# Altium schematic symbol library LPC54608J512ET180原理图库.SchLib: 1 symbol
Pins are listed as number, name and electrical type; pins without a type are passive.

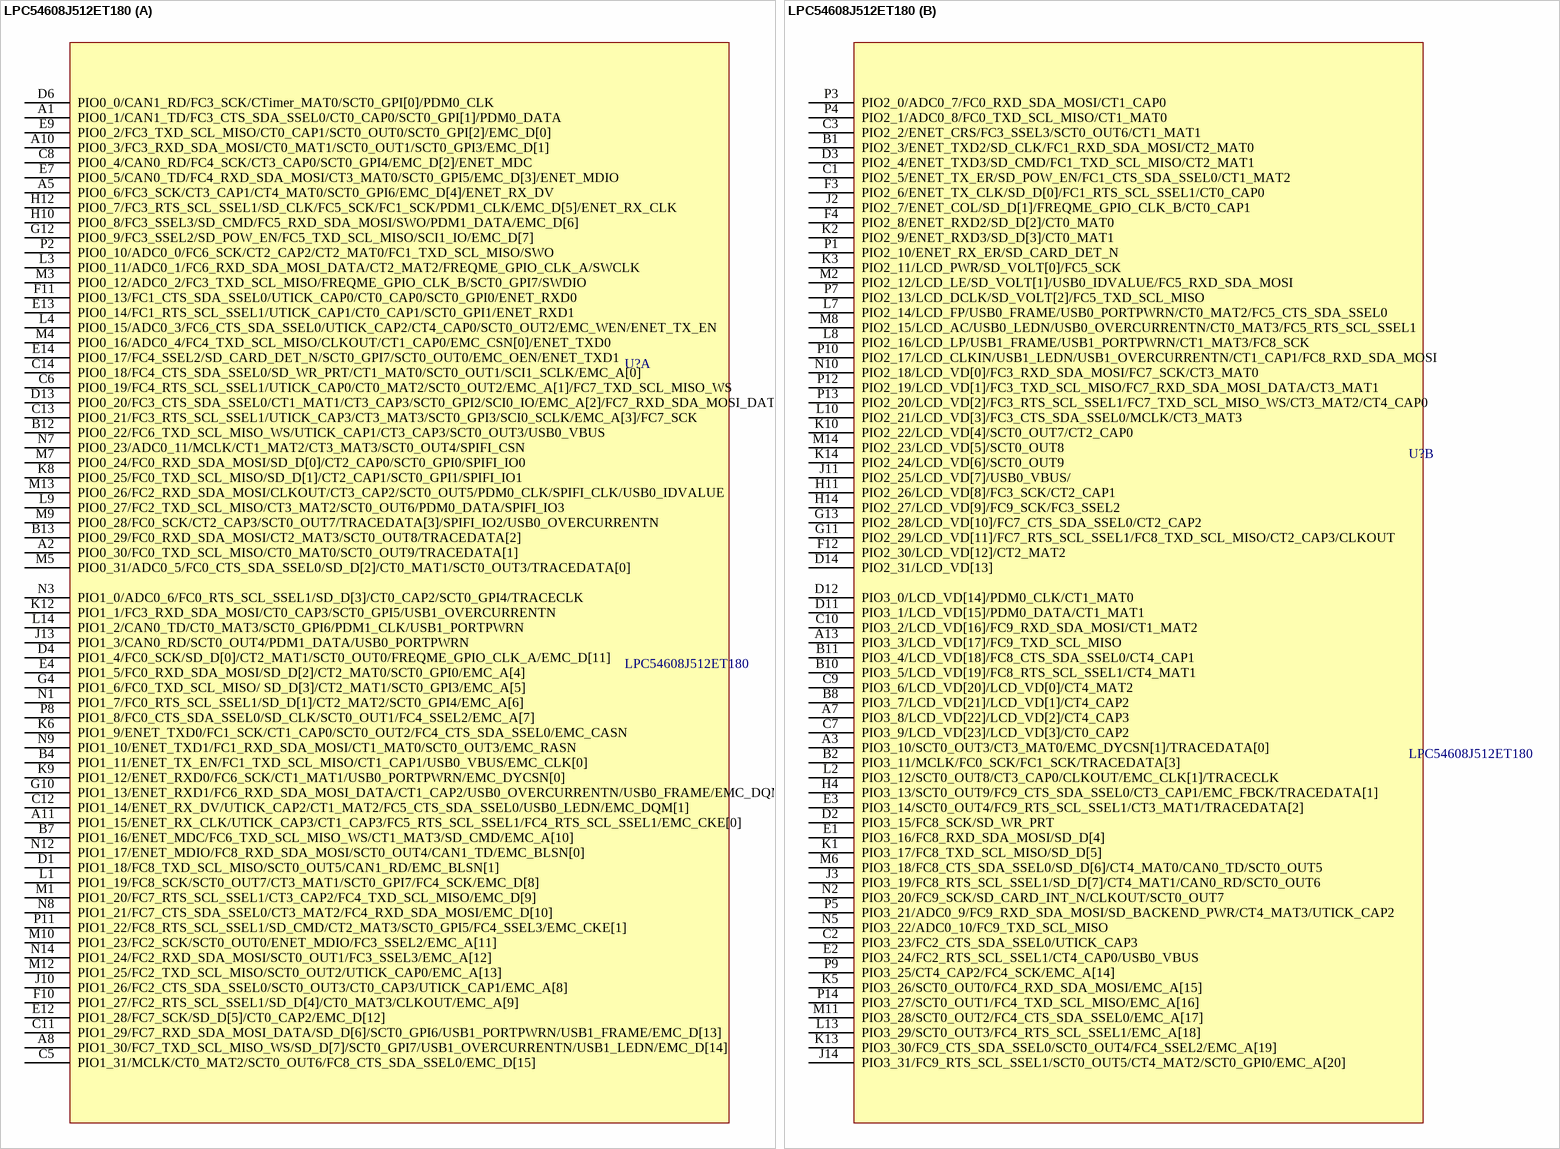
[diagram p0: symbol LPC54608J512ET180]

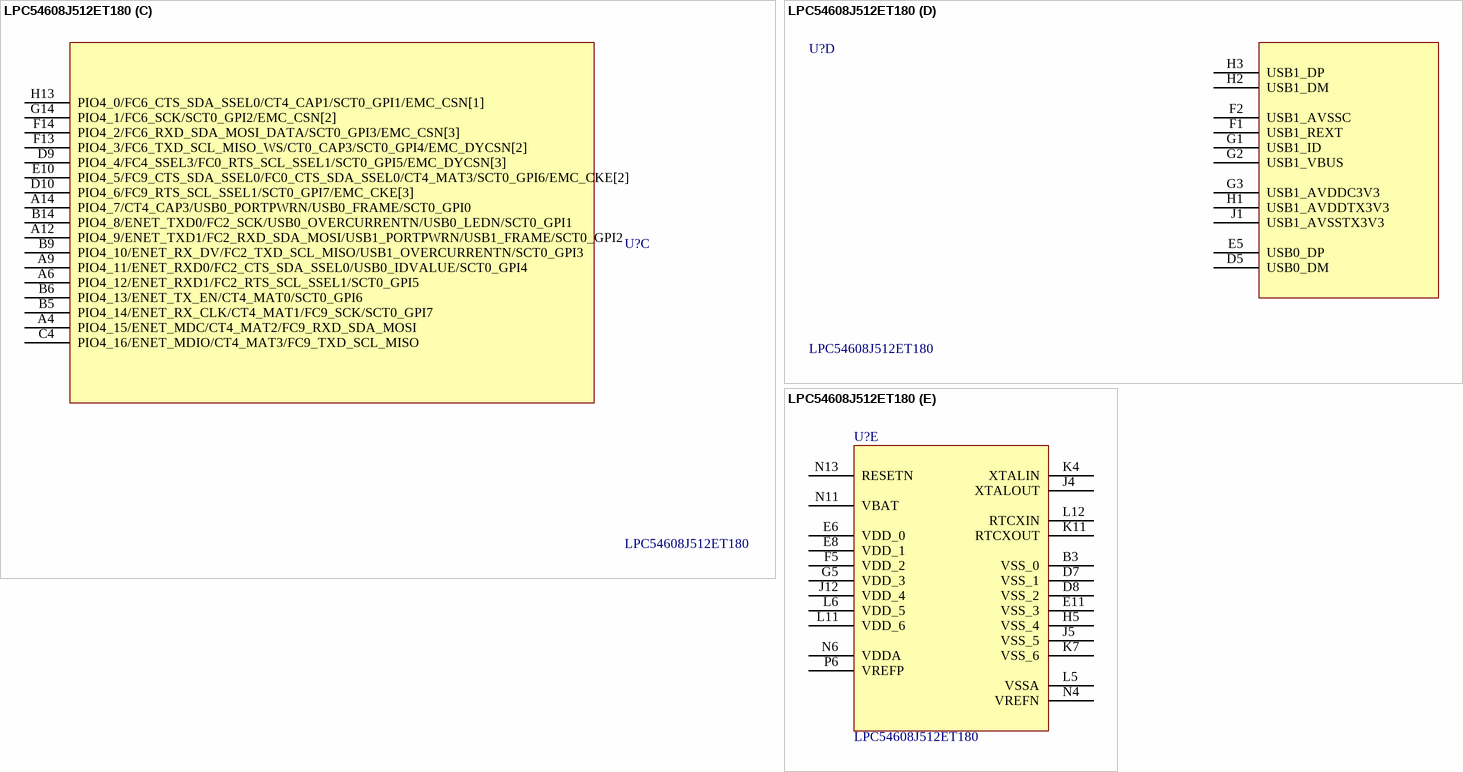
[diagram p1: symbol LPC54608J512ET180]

## LPC54608J512ET180
designator U?
LPC54608J512ET180,TFBGA180,NXP,RoHS; 物料代码: 1.05.02.0192; 名称: 集成电路(临时); 贴片和直插: SMT; PCB备注: 170314lmd; 器件优选方案: 临时/偏门物料/不主推物料，谨慎选用
footprint BGA180C80P14x14
part A pins: A1 PIO0_1/CAN1_TD/FC3_CTS_SDA_SSEL0/CT0_CAP0/SCT0_GPI[1]/PDM0_DATA, A2 PIO0_30/FC0_TXD_SCL_MISO/CT0_MAT0/SCT0_OUT9/TRACEDATA[1], A5 PIO0_6/FC3_SCK/CT3_CAP1/CT4_MAT0/SCT0_GPI6/EMC_D[4]/ENET_RX_DV, A8 PIO1_30/FC7_TXD_SCL_MISO_WS/SD_D[7]/SCT0_GPI7/USB1_OVERCURRENTN/USB1_LEDN/EMC_D[14], A10 PIO0_3/FC3_RXD_SDA_MOSI/CT0_MAT1/SCT0_OUT1/SCT0_GPI3/EMC_D[1], A11 PIO1_15/ENET_RX_CLK/UTICK_CAP3/CT1_CAP3/FC5_RTS_SCL_SSEL1/FC4_RTS_SCL_SSEL1/EMC_CKE[0], B4 PIO1_11/ENET_TX_EN/FC1_TXD_SCL_MISO/CT1_CAP1/USB0_VBUS/EMC_CLK[0], B7 PIO1_16/ENET_MDC/FC6_TXD_SCL_MISO_WS/CT1_MAT3/SD_CMD/EMC_A[10], B12 PIO0_22/FC6_TXD_SCL_MISO_WS/UTICK_CAP1/CT3_CAP3/SCT0_OUT3/USB0_VBUS, B13 PIO0_29/FC0_RXD_SDA_MOSI/CT2_MAT3/SCT0_OUT8/TRACEDATA[2], C5 PIO1_31/MCLK/CT0_MAT2/SCT0_OUT6/FC8_CTS_SDA_SSEL0/EMC_D[15], C6 PIO0_19/FC4_RTS_SCL_SSEL1/UTICK_CAP0/CT0_MAT2/SCT0_OUT2/EMC_A[1]/FC7_TXD_SCL_MISO_WS, C8 PIO0_4/CAN0_RD/FC4_SCK/CT3_CAP0/SCT0_GPI4/EMC_D[2]/ENET_MDC, C11 PIO1_29/FC7_RXD_SDA_MOSI_DATA/SD_D[6]/SCT0_GPI6/USB1_PORTPWRN/USB1_FRAME/EMC_D[13], C12 PIO1_14/ENET_RX_DV/UTICK_CAP2/CT1_MAT2/FC5_CTS_SDA_SSEL0/USB0_LEDN/EMC_DQM[1], C13 PIO0_21/FC3_RTS_SCL_SSEL1/UTICK_CAP3/CT3_MAT3/SCT0_GPI3/SCI0_SCLK/EMC_A[3]/FC7_SCK, C14 PIO0_18/FC4_CTS_SDA_SSEL0/SD_WR_PRT/CT1_MAT0/SCT0_OUT1/SCI1_SCLK/EMC_A[0], D1 PIO1_18/FC8_TXD_SCL_MISO/SCT0_OUT5/CAN1_RD/EMC_BLSN[1], D4 PIO1_4/FC0_SCK/SD_D[0]/CT2_MAT1/SCT0_OUT0/FREQME_GPIO_CLK_A/EMC_D[11], D6 PIO0_0/CAN1_RD/FC3_SCK/CTimer_MAT0/SCT0_GPI[0]/PDM0_CLK, D13 PIO0_20/FC3_CTS_SDA_SSEL0/CT1_MAT1/CT3_CAP3/SCT0_GPI2/SCI0_IO/EMC_A[2]/FC7_RXD_SDA_MOSI_DATA, E4 PIO1_5/FC0_RXD_SDA_MOSI/SD_D[2]/CT2_MAT0/SCT0_GPI0/EMC_A[4], E7 PIO0_5/CAN0_TD/FC4_RXD_SDA_MOSI/CT3_MAT0/SCT0_GPI5/EMC_D[3]/ENET_MDIO, E9 PIO0_2/FC3_TXD_SCL_MISO/CT0_CAP1/SCT0_OUT0/SCT0_GPI[2]/EMC_D[0], E12 PIO1_28/FC7_SCK/SD_D[5]/CT0_CAP2/EMC_D[12], E13 PIO0_14/FC1_RTS_SCL_SSEL1/UTICK_CAP1/CT0_CAP1/SCT0_GPI1/ENET_RXD1, E14 PIO0_17/FC4_SSEL2/SD_CARD_DET_N/SCT0_GPI7/SCT0_OUT0/EMC_OEN/ENET_TXD1, F10 PIO1_27/FC2_RTS_SCL_SSEL1/SD_D[4]/CT0_MAT3/CLKOUT/EMC_A[9], F11 PIO0_13/FC1_CTS_SDA_SSEL0/UTICK_CAP0/CT0_CAP0/SCT0_GPI0/ENET_RXD0, G4 PIO1_6/FC0_TXD_SCL_MISO/ SD_D[3]/CT2_MAT1/SCT0_GPI3/EMC_A[5], G10 PIO1_13/ENET_RXD1/FC6_RXD_SDA_MOSI_DATA/CT1_CAP2/USB0_OVERCURRENTN/USB0_FRAME/EMC_DQM[0], G12 PIO0_9/FC3_SSEL2/SD_POW_EN/FC5_TXD_SCL_MISO/SCI1_IO/EMC_D[7], H10 PIO0_8/FC3_SSEL3/SD_CMD/FC5_RXD_SDA_MOSI/SWO/PDM1_DATA/EMC_D[6], H12 PIO0_7/FC3_RTS_SCL_SSEL1/SD_CLK/FC5_SCK/FC1_SCK/PDM1_CLK/EMC_D[5]/ENET_RX_CLK, J10 PIO1_26/FC2_CTS_SDA_SSEL0/SCT0_OUT3/CT0_CAP3/UTICK_CAP1/EMC_A[8], J13 PIO1_3/CAN0_RD/SCT0_OUT4/PDM1_DATA/USB0_PORTPWRN, K6 PIO1_9/ENET_TXD0/FC1_SCK/CT1_CAP0/SCT0_OUT2/FC4_CTS_SDA_SSEL0/EMC_CASN, K8 PIO0_25/FC0_TXD_SCL_MISO/SD_D[1]/CT2_CAP1/SCT0_GPI1/SPIFI_IO1, K9 PIO1_12/ENET_RXD0/FC6_SCK/CT1_MAT1/USB0_PORTPWRN/EMC_DYCSN[0], K12 PIO1_1/FC3_RXD_SDA_MOSI/CT0_CAP3/SCT0_GPI5/USB1_OVERCURRENTN, L1 PIO1_19/FC8_SCK/SCT0_OUT7/CT3_MAT1/SCT0_GPI7/FC4_SCK/EMC_D[8], L3 PIO0_11/ADC0_1/FC6_RXD_SDA_MOSI_DATA/CT2_MAT2/FREQME_GPIO_CLK_A/SWCLK, L4 PIO0_15/ADC0_3/FC6_CTS_SDA_SSEL0/UTICK_CAP2/CT4_CAP0/SCT0_OUT2/EMC_WEN/ENET_TX_EN, L9 PIO0_27/FC2_TXD_SCL_MISO/CT3_MAT2/SCT0_OUT6/PDM0_DATA/SPIFI_IO3, L14 PIO1_2/CAN0_TD/CT0_MAT3/SCT0_GPI6/PDM1_CLK/USB1_PORTPWRN, M1 PIO1_20/FC7_RTS_SCL_SSEL1/CT3_CAP2/FC4_TXD_SCL_MISO/EMC_D[9], M3 PIO0_12/ADC0_2/FC3_TXD_SCL_MISO/FREQME_GPIO_CLK_B/SCT0_GPI7/SWDIO, M4 PIO0_16/ADC0_4/FC4_TXD_SCL_MISO/CLKOUT/CT1_CAP0/EMC_CSN[0]/ENET_TXD0, M5 PIO0_31/ADC0_5/FC0_CTS_SDA_SSEL0/SD_D[2]/CT0_MAT1/SCT0_OUT3/TRACEDATA[0], M7 PIO0_24/FC0_RXD_SDA_MOSI/SD_D[0]/CT2_CAP0/SCT0_GPI0/SPIFI_IO0, M9 PIO0_28/FC0_SCK/CT2_CAP3/SCT0_OUT7/TRACEDATA[3]/SPIFI_IO2/USB0_OVERCURRENTN, M10 PIO1_23/FC2_SCK/SCT0_OUT0/ENET_MDIO/FC3_SSEL2/EMC_A[11], M12 PIO1_25/FC2_TXD_SCL_MISO/SCT0_OUT2/UTICK_CAP0/EMC_A[13], M13 PIO0_26/FC2_RXD_SDA_MOSI/CLKOUT/CT3_CAP2/SCT0_OUT5/PDM0_CLK/SPIFI_CLK/USB0_IDVALUE, N1 PIO1_7/FC0_RTS_SCL_SSEL1/SD_D[1]/CT2_MAT2/SCT0_GPI4/EMC_A[6], N3 PIO1_0/ADC0_6/FC0_RTS_SCL_SSEL1/SD_D[3]/CT0_CAP2/SCT0_GPI4/TRACECLK, N7 PIO0_23/ADC0_11/MCLK/CT1_MAT2/CT3_MAT3/SCT0_OUT4/SPIFI_CSN, N8 PIO1_21/FC7_CTS_SDA_SSEL0/CT3_MAT2/FC4_RXD_SDA_MOSI/EMC_D[10], N9 PIO1_10/ENET_TXD1/FC1_RXD_SDA_MOSI/CT1_MAT0/SCT0_OUT3/EMC_RASN, N12 PIO1_17/ENET_MDIO/FC8_RXD_SDA_MOSI/SCT0_OUT4/CAN1_TD/EMC_BLSN[0], N14 PIO1_24/FC2_RXD_SDA_MOSI/SCT0_OUT1/FC3_SSEL3/EMC_A[12], P2 PIO0_10/ADC0_0/FC6_SCK/CT2_CAP2/CT2_MAT0/FC1_TXD_SCL_MISO/SWO, P8 PIO1_8/FC0_CTS_SDA_SSEL0/SD_CLK/SCT0_OUT1/FC4_SSEL2/EMC_A[7], P11 PIO1_22/FC8_RTS_SCL_SSEL1/SD_CMD/CT2_MAT3/SCT0_GPI5/FC4_SSEL3/EMC_CKE[1]
part B pins: A3 PIO3_10/SCT0_OUT3/CT3_MAT0/EMC_DYCSN[1]/TRACEDATA[0], A7 PIO3_8/LCD_VD[22]/LCD_VD[2]/CT4_CAP3, A13 PIO3_3/LCD_VD[17]/FC9_TXD_SCL_MISO, B1 PIO2_3/ENET_TXD2/SD_CLK/FC1_RXD_SDA_MOSI/CT2_MAT0, B2 PIO3_11/MCLK/FC0_SCK/FC1_SCK/TRACEDATA[3], B8 PIO3_7/LCD_VD[21]/LCD_VD[1]/CT4_CAP2, B10 PIO3_5/LCD_VD[19]/FC8_RTS_SCL_SSEL1/CT4_MAT1, B11 PIO3_4/LCD_VD[18]/FC8_CTS_SDA_SSEL0/CT4_CAP1, C1 PIO2_5/ENET_TX_ER/SD_POW_EN/FC1_CTS_SDA_SSEL0/CT1_MAT2, C2 PIO3_23/FC2_CTS_SDA_SSEL0/UTICK_CAP3, C3 PIO2_2/ENET_CRS/FC3_SSEL3/SCT0_OUT6/CT1_MAT1, C7 PIO3_9/LCD_VD[23]/LCD_VD[3]/CT0_CAP2, C9 PIO3_6/LCD_VD[20]/LCD_VD[0]/CT4_MAT2, C10 PIO3_2/LCD_VD[16]/FC9_RXD_SDA_MOSI/CT1_MAT2, D2 PIO3_15/FC8_SCK/SD_WR_PRT, D3 PIO2_4/ENET_TXD3/SD_CMD/FC1_TXD_SCL_MISO/CT2_MAT1, D11 PIO3_1/LCD_VD[15]/PDM0_DATA/CT1_MAT1, D12 PIO3_0/LCD_VD[14]/PDM0_CLK/CT1_MAT0, D14 PIO2_31/LCD_VD[13], E1 PIO3_16/FC8_RXD_SDA_MOSI/SD_D[4], E2 PIO3_24/FC2_RTS_SCL_SSEL1/CT4_CAP0/USB0_VBUS, E3 PIO3_14/SCT0_OUT4/FC9_RTS_SCL_SSEL1/CT3_MAT1/TRACEDATA[2], F3 PIO2_6/ENET_TX_CLK/SD_D[0]/FC1_RTS_SCL_SSEL1/CT0_CAP0, F4 PIO2_8/ENET_RXD2/SD_D[2]/CT0_MAT0, F12 PIO2_30/LCD_VD[12]/CT2_MAT2, G11 PIO2_29/LCD_VD[11]/FC7_RTS_SCL_SSEL1/FC8_TXD_SCL_MISO/CT2_CAP3/CLKOUT, G13 PIO2_28/LCD_VD[10]/FC7_CTS_SDA_SSEL0/CT2_CAP2, H4 PIO3_13/SCT0_OUT9/FC9_CTS_SDA_SSEL0/CT3_CAP1/EMC_FBCK/TRACEDATA[1], H11 PIO2_26/LCD_VD[8]/FC3_SCK/CT2_CAP1, H14 PIO2_27/LCD_VD[9]/FC9_SCK/FC3_SSEL2, J2 PIO2_7/ENET_COL/SD_D[1]/FREQME_GPIO_CLK_B/CT0_CAP1, J3 PIO3_19/FC8_RTS_SCL_SSEL1/SD_D[7]/CT4_MAT1/CAN0_RD/SCT0_OUT6, J11 PIO2_25/LCD_VD[7]/USB0_VBUS/, J14 PIO3_31/FC9_RTS_SCL_SSEL1/SCT0_OUT5/CT4_MAT2/SCT0_GPI0/EMC_A[20], K1 PIO3_17/FC8_TXD_SCL_MISO/SD_D[5], K2 PIO2_9/ENET_RXD3/SD_D[3]/CT0_MAT1, K3 PIO2_11/LCD_PWR/SD_VOLT[0]/FC5_SCK, K5 PIO3_26/SCT0_OUT0/FC4_RXD_SDA_MOSI/EMC_A[15], K10 PIO2_22/LCD_VD[4]/SCT0_OUT7/CT2_CAP0, K13 PIO3_30/FC9_CTS_SDA_SSEL0/SCT0_OUT4/FC4_SSEL2/EMC_A[19], K14 PIO2_24/LCD_VD[6]/SCT0_OUT9, L2 PIO3_12/SCT0_OUT8/CT3_CAP0/CLKOUT/EMC_CLK[1]/TRACECLK, L7 PIO2_14/LCD_FP/USB0_FRAME/USB0_PORTPWRN/CT0_MAT2/FC5_CTS_SDA_SSEL0, L8 PIO2_16/LCD_LP/USB1_FRAME/USB1_PORTPWRN/CT1_MAT3/FC8_SCK, L10 PIO2_21/LCD_VD[3]/FC3_CTS_SDA_SSEL0/MCLK/CT3_MAT3, L13 PIO3_29/SCT0_OUT3/FC4_RTS_SCL_SSEL1/EMC_A[18], M2 PIO2_12/LCD_LE/SD_VOLT[1]/USB0_IDVALUE/FC5_RXD_SDA_MOSI, M6 PIO3_18/FC8_CTS_SDA_SSEL0/SD_D[6]/CT4_MAT0/CAN0_TD/SCT0_OUT5, M8 PIO2_15/LCD_AC/USB0_LEDN/USB0_OVERCURRENTN/CT0_MAT3/FC5_RTS_SCL_SSEL1, M11 PIO3_28/SCT0_OUT2/FC4_CTS_SDA_SSEL0/EMC_A[17], M14 PIO2_23/LCD_VD[5]/SCT0_OUT8, N2 PIO3_20/FC9_SCK/SD_CARD_INT_N/CLKOUT/SCT0_OUT7, N5 PIO3_22/ADC0_10/FC9_TXD_SCL_MISO, N10 PIO2_18/LCD_VD[0]/FC3_RXD_SDA_MOSI/FC7_SCK/CT3_MAT0, P1 PIO2_10/ENET_RX_ER/SD_CARD_DET_N, P3 PIO2_0/ADC0_7/FC0_RXD_SDA_MOSI/CT1_CAP0, P4 PIO2_1/ADC0_8/FC0_TXD_SCL_MISO/CT1_MAT0, P5 PIO3_21/ADC0_9/FC9_RXD_SDA_MOSI/SD_BACKEND_PWR/CT4_MAT3/UTICK_CAP2, P7 PIO2_13/LCD_DCLK/SD_VOLT[2]/FC5_TXD_SCL_MISO, P9 PIO3_25/CT4_CAP2/FC4_SCK/EMC_A[14], P10 PIO2_17/LCD_CLKIN/USB1_LEDN/USB1_OVERCURRENTN/CT1_CAP1/FC8_RXD_SDA_MOSI, P12 PIO2_19/LCD_VD[1]/FC3_TXD_SCL_MISO/FC7_RXD_SDA_MOSI_DATA/CT3_MAT1, P13 PIO2_20/LCD_VD[2]/FC3_RTS_SCL_SSEL1/FC7_TXD_SCL_MISO_WS/CT3_MAT2/CT4_CAP0, P14 PIO3_27/SCT0_OUT1/FC4_TXD_SCL_MISO/EMC_A[16]
part C pins: A4 PIO4_15/ENET_MDC/CT4_MAT2/FC9_RXD_SDA_MOSI, A6 PIO4_12/ENET_RXD1/FC2_RTS_SCL_SSEL1/SCT0_GPI5, A9 PIO4_11/ENET_RXD0/FC2_CTS_SDA_SSEL0/USB0_IDVALUE/SCT0_GPI4, A12 PIO4_9/ENET_TXD1/FC2_RXD_SDA_MOSI/USB1_PORTPWRN/USB1_FRAME/SCT0_GPI2, A14 PIO4_7/CT4_CAP3/USB0_PORTPWRN/USB0_FRAME/SCT0_GPI0, B5 PIO4_14/ENET_RX_CLK/CT4_MAT1/FC9_SCK/SCT0_GPI7, B6 PIO4_13/ENET_TX_EN/CT4_MAT0/SCT0_GPI6, B9 PIO4_10/ENET_RX_DV/FC2_TXD_SCL_MISO/USB1_OVERCURRENTN/SCT0_GPI3, B14 PIO4_8/ENET_TXD0/FC2_SCK/USB0_OVERCURRENTN/USB0_LEDN/SCT0_GPI1, C4 PIO4_16/ENET_MDIO/CT4_MAT3/FC9_TXD_SCL_MISO, D9 PIO4_4/FC4_SSEL3/FC0_RTS_SCL_SSEL1/SCT0_GPI5/EMC_DYCSN[3], D10 PIO4_6/FC9_RTS_SCL_SSEL1/SCT0_GPI7/EMC_CKE[3], E10 PIO4_5/FC9_CTS_SDA_SSEL0/FC0_CTS_SDA_SSEL0/CT4_MAT3/SCT0_GPI6/EMC_CKE[2], F13 PIO4_3/FC6_TXD_SCL_MISO_WS/CT0_CAP3/SCT0_GPI4/EMC_DYCSN[2], F14 PIO4_2/FC6_RXD_SDA_MOSI_DATA/SCT0_GPI3/EMC_CSN[3], G14 PIO4_1/FC6_SCK/SCT0_GPI2/EMC_CSN[2], H13 PIO4_0/FC6_CTS_SDA_SSEL0/CT4_CAP1/SCT0_GPI1/EMC_CSN[1]
part D pins: D5 USB0_DM, E5 USB0_DP, F1 USB1_REXT, F2 USB1_AVSSC, G1 USB1_ID, G2 USB1_VBUS, G3 USB1_AVDDC3V3, H1 USB1_AVDDTX3V3, H2 USB1_DM, H3 USB1_DP, J1 USB1_AVSSTX3V3
part E pins: B3 VSS_0, D7 VSS_1, D8 VSS_2, E6 VDD_0, E8 VDD_1, E11 VSS_3, F5 VDD_2, G5 VDD_3, H5 VSS_4, J4 XTALOUT, J5 VSS_5, J12 VDD_4, K4 XTALIN, K7 VSS_6, K11 RTCXOUT, L5 VSSA, L6 VDD_5, L11 VDD_6, L12 RTCXIN, N4 VREFN, N6 VDDA, N11 VBAT, N13 RESETN, P6 VREFP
